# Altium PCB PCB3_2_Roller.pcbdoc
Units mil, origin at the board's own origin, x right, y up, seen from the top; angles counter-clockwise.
Board outline 1564.33 x 2054.84 mil, 2 copper layers (Top Layer, Bottom Layer), stack 2.757 mil thick; 8 components, 9 nets, 34 pads, 9 vias.
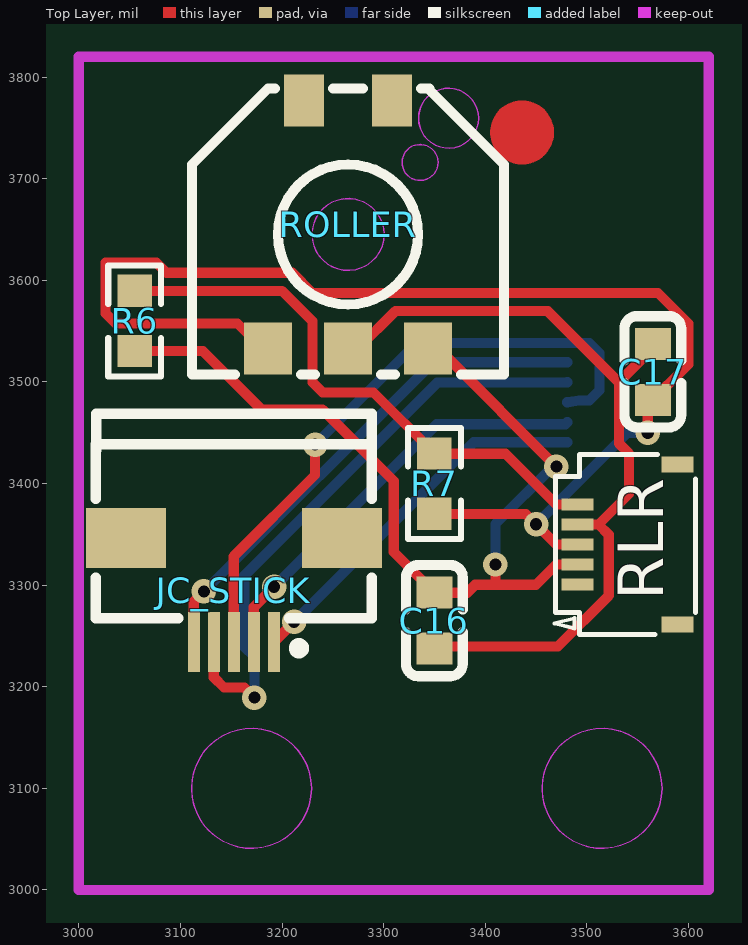
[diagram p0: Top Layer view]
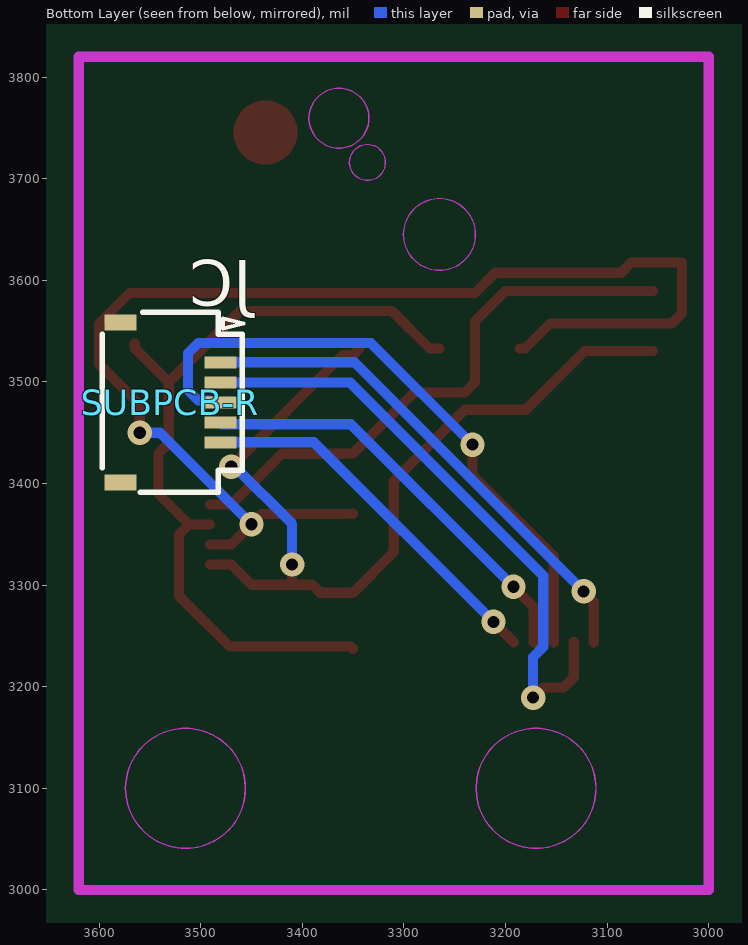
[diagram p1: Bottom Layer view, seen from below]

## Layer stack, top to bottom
Top Solder Mask Layer: solder mask 0.394, Dk 3.3
Top Layer: signal copper 1.379
Bottom Layer: signal copper 1.378
Bottom Solder Mask Layer: solder mask 0.394, Dk 3.3

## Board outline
4314.33,2750 2750,2750 2750,4804.84 4314.33,4804.84

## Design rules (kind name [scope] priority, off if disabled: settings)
BoardOutlineClearance Default [All] p0: genericclearance=10 ignorepadtopadclearanceinfootprint=FALSE except(0: Arc-SplitContinuation Track-SplitContinuation SMDPad-SplitContinuation THPad-SplitContinuation Via-SplitContinuation Fill-SplitContinuation Poly-SplitContinuation Region-SplitContinuation Text-SplitContinuation)
BoardOutlineClearance otherClearance [All] p0: genericclearance=10 ignorepadtopadclearanceinfootprint=FALSE except(0: Arc-SplitContinuation Track-SplitContinuation SMDPad-SplitContinuation THPad-SplitContinuation Via-SplitContinuation Fill-SplitContinuation Poly-SplitContinuation Region-SplitContinuation Text-SplitContinuation)
Clearance Default [All] p1: gap=7 ignorepadtopadclearanceinfootprint=FALSE
Clearance otherClearance [All] p1: gap=7 ignorepadtopadclearanceinfootprint=FALSE
DiffPairsRouting differentialPair [All] p1: maxuncoupledlength=10 minlimit=5 maxlimit=Infinity mostfreqgap=6 toplayer_minwidth=5 toplayer_prefwidth=100 toplayer_maxwidth=100 bottomlayer_minwidth=5 bottomlayer_prefwidth=100 bottomlayer_maxwidth=100
PasteMaskExpansion pasteMaskExpansion [All] p1: expansion=0
PlaneConnect innerPlane [All] p1: planeconnectstyle=Relief reliefexpansion=20 reliefentries=4 reliefconductorwidth=10 reliefairgap=10
PolygonConnect copperRegion [All] p1: connectstyle=Relief reliefentries=4 reliefconductorwidth=10 polygonreliefangle="90 Angle" airgapwidth=10
RoutingVias Default [All] p1: viastyle="Through Hole" holewidth=12.008000000000001 minholewidth=12.008000000000001 maxholewidth=1181 width=12.008000000000001 minwidth=12.008000000000001 maxwidth=1181
SolderMaskExpansion Common [IsVia] p1: useseparateexpansions=TRUE expansion=-1000 expansionbottom=-1000
SolderMaskExpansion Common [All] p2: useseparateexpansions=TRUE expansion=2 expansionbottom=2
Width Default [All] p1: maxlimit=1000 minlimit=10 preferedwidth=10

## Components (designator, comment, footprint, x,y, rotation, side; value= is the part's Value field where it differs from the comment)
C16 "0.1uF" C0603 3350,3265 r90 top
C17 "0.1uF" C0603 3565,3510 r90 top
JC_STICK "JOYCON STICK" 任天堂SWITCH摇杆 3152.52,3295 r180 top
R6 "10kΩ" R0603 3055,3560 r270 top
R7 "10kΩ" R0603 3350,3400 r270 top
RLR "Roller" CONN-SMD_5P-P0.50_HCTL_HC-FPC-05-09-5RLTAG 3540,3340 r90 top
ROLLER "YTS23-E0035-A1B" SW-SMD_YTS23-E0035-A1B 3265,3655 r0 top
SUBPCB-R "Roller" CONN-SMD_5P-P0.50_HCTL_HC-FPC-05-09-5RLTAG 3530,3480 r270 bottom

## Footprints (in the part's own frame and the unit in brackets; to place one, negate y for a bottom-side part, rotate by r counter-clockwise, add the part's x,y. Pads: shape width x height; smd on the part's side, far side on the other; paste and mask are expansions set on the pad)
C0603 [mm]
  rect 0.8x0.9 smd paste+0 mask+0.051: 1(-0.7,0) 2(0.7,0)
  silkscreen extent -1.39,-0.71 1.39,0.71
CONN-SMD_5P-P0.50_HCTL_HC-FPC-05-09-5RLTAG [mm]
  rect 0.3x0.8 smd paste+0 mask+0.051: 1(-1,1.25) 2(-0.5,1.25) 3(0,1.25) 4(0.5,1.25) 5(1,1.25)
  rect 0.4x0.8 smd paste+0 mask+0.051: 6(2,-1.25) 7(-2,-1.25)
  silkscreen extent -2.25,-1.7 2.25,1.83
R0603 [mil]
  rect 31.75x34.02 smd paste-3937.01 mask+2: 1(-29.66,0) 2(29.66,0)
  silkscreen extent -55,-26 55,26
SW-SMD_YTS23-E0035-A1B [mm]
  rect 1.2x1.3 smd paste+0 mask+0.051: A(-2,-3.1) B(2,-3.1) C(0,-3.1)
  rect 1x1.3 smd paste+0 mask+0.051: D(-1.1,3.1) E(1.1,3.1)
  Top Layer lines w0.8: 3.95,2.3 cw(c4.35,2.3) 4.75,2.3 cw(c4.35,2.3) 3.95,2.3
  Board Outline Layer circle w0.003: c0,-0.25 r0.9
  Board Outline Layer circle w0.003: c1.8,1.55 r0.45
  Board Outline Layer region: 0.9,-0.25 0.811,-0.641 0.561,-0.954 0.2,-1.128 -0.2,-1.128 -0.561,-0.954 -0.811,-0.641 -0.9,-0.25 -0.9,-0.25 -0.811,0.14 -0.561,0.453 -0.2,0.627 0.2,0.627 0.561,0.453 0.811,0.14 0.9,-0.25
  Board Outline Layer region: 0.9,-0.25 0.811,-0.641 0.561,-0.954 0.2,-1.128 -0.2,-1.128 -0.561,-0.954 -0.811,-0.641 -0.9,-0.25 -0.9,-0.25 -0.811,0.14 -0.561,0.453 -0.2,0.627 0.2,0.627 0.561,0.453 0.811,0.14 0.9,-0.25
  Board Outline Layer region: 2.25,1.55 2.206,1.355 2.081,1.198 1.9,1.111 1.7,1.111 1.52,1.198 1.395,1.355 1.35,1.55 1.35,1.55 1.395,1.745 1.52,1.902 1.7,1.989 1.9,1.989 2.081,1.902 2.206,1.745 2.25,1.55
  Board Outline Layer region: 2.25,1.55 2.206,1.355 2.081,1.198 1.9,1.111 1.7,1.111 1.52,1.198 1.395,1.355 1.35,1.55 1.35,1.55 1.395,1.745 1.52,1.902 1.7,1.989 1.9,1.989 2.081,1.902 2.206,1.745 2.25,1.55
  silkscreen extent -3.9,-3.75 3.9,3.4
任天堂SWITCH摇杆 [mm]
  rect 0.3x1.5 smd paste+0 mask+0.051: 1(-1,1.3) 2(-0.5,1.3) 3(0,1.3) 4(0.5,1.3) 5(1,1.3)
  rect 2x1.5 smd paste+0 mask+0.051: 6(-2.7,-1.3) 7(2.7,-1.3)
  Board Outline Layer circle w0.003: c-21.25,-29.93 r0.6
  Board Outline Layer circle w0.003: c-5.37,-11.8 r0.75
  Board Outline Layer region: -21.85,-29.93 -21.79,-29.67 -21.624,-29.461 -21.383,-29.345 -21.116,-29.345 -20.876,-29.461 -20.709,-29.67 -20.65,-29.93 -20.65,-29.93 -20.709,-30.19 -20.876,-30.399 -21.116,-30.515 -21.383,-30.515 -21.624,-30.399 -21.79,-30.19 -21.85,-29.93
  Board Outline Layer region: -21.85,-29.93 -21.79,-29.67 -21.624,-29.461 -21.383,-29.345 -21.116,-29.345 -20.876,-29.461 -20.709,-29.67 -20.65,-29.93 -20.65,-29.93 -20.709,-30.19 -20.876,-30.399 -21.116,-30.515 -21.383,-30.515 -21.624,-30.399 -21.79,-30.19 -21.85,-29.93
  Board Outline Layer region: -6.12,-11.8 -6.046,-11.475 -5.837,-11.214 -5.537,-11.069 -5.203,-11.069 -4.902,-11.214 -4.694,-11.475 -4.62,-11.8 -4.62,-11.8 -4.694,-12.125 -4.902,-12.386 -5.203,-12.531 -5.537,-12.531 -5.837,-12.386 -6.046,-12.125 -6.12,-11.8
  Board Outline Layer region: -6.12,-11.8 -6.046,-11.475 -5.837,-11.214 -5.537,-11.069 -5.203,-11.069 -4.902,-11.214 -4.694,-11.475 -4.62,-11.8 -4.62,-11.8 -4.694,-12.125 -4.902,-12.386 -5.203,-12.531 -5.537,-12.531 -5.837,-12.386 -6.046,-12.125 -6.12,-11.8
  silkscreen extent -3.45,-4.41 3.45,1.58

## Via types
v1: diameter 24.02, hole 12.01, Top Layer to Bottom Layer, 9 vias

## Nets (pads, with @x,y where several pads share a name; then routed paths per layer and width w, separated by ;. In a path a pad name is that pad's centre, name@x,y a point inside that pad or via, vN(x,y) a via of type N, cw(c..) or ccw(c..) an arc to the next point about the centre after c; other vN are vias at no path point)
JC_STICK1_1: JC_STICK.1 SUBPCB-R.5 | length 370.4
  Top Layer w10: JC_STICK.1 v1(3211.89,3263.82)
  Bottom Layer w10: v1(3211.89,3263.82) 3388.7,3440.63 SUBPCB-R.5
JC_STICK1_2: JC_STICK.2 SUBPCB-R.4 | length 418.5
  Top Layer w10: JC_STICK.2 3172.21,3278.35 v1(3192.21,3298.35)
  Bottom Layer w10: v1(3192.21,3298.35) 3352.21,3458.35 3478.82,3458.35 SUBPCB-R.4
JC_STICK1_3: JC_STICK.3 SUBPCB-R.3 | length 625.8
  Top Layer w10: JC_STICK.3 3152.52,3328.35 3232.52,3408.35 v1(3232.52,3438.35)
  Bottom Layer w10: v1(3232.52,3438.35) 3332.52,3538.35 3502.52,3538.35 3512.52,3528.35 3512.52,3491.73 3502.52,3481.73 3492.52,3481.73 SUBPCB-R.3
JC_STICK1_4: JC_STICK.4 SUBPCB-R.2 | length 603.8
  Top Layer w10: JC_STICK.4 3132.84,3209.29 3142.84,3199.29 3162.84,3199.29 v1(3172.84,3189.29)
  Bottom Layer w10: v1(3172.84,3189.29) 3172.84,3229.29 3162.84,3239.29 3162.84,3309.29 3352.84,3499.29 3480.39,3499.29 SUBPCB-R.2
JC_STICK1_5: JC_STICK.5 SUBPCB-R.1 | length 505.2
  Top Layer w10: JC_STICK.5 3113.15,3283.82 v1(3123.15,3293.82)
  Bottom Layer w10: v1(3123.15,3293.82) 3348.7,3519.37 SUBPCB-R.1
SUB_3V3: R6.1 R7.1 RLR.5 | length 557.9
  Top Layer w10: R6.1 3200,3589.66 3230,3559.66 3230,3499.66 3240,3489.66 3290,3489.66 R7.1 3360.04,3429.37 3420.04,3429.37 3470.04,3379.37 RLR.5
SUB_A: C17.1 R7.2 RLR.3 ROLLER.A | length 1247.5
  Top Layer w10: ROLLER.A@3186.26,3532.95 3180.8,3532.95 3156.26,3557.49 3036.26,3557.49 3026.26,3567.49 3026.26,3617.49 3076.26,3617.49 3086.26,3607.49 3210.04,3607.49 3230.04,3587.49 3570.04,3587.49 3600.04,3557.49 3600.04,3517.49 3560.04,3477.49 v1(3560.04,3450) ; R7.2 3360.04,3370 3440.04,3370 v1(3450.04,3360) 3470.04,3340 RLR.3
  Bottom Layer w10: v1(3450.04,3360) 3540.04,3450 v1(3560.04,3450)
SUB_B: C16.2 R6.2 RLR.2 ROLLER.B | length 904.6
  Top Layer w10: R6.2 3122.23,3530.34 3180,3472.56 3240,3472.56 3310,3402.56 3310,3332.56 C16.2 3382.3,3292.56 3390.04,3300.31 3410.04,3300.31 ; ROLLER.B@3343.74,3532.95 3350.04,3526.65 3360.04,3526.65 v1(3470.04,3416.65) ; v1(3410.04,3320.31) 3410.04,3300.31 ; RLR.2 3470.04,3320.31 3450.04,3300.31 3410.04,3300.31
  Bottom Layer w10: v1(3410.04,3320.31) 3410.04,3360.31 3466.38,3416.65 v1(3470.04,3416.65)
SUB_GND: C16.1 C17.2 RLR.4 ROLLER.C | length 807.1
  Top Layer w10: ROLLER.C@3265,3532.95 3274.81,3532.95 3311.54,3569.68 3461.54,3569.68 3531.54,3499.68 ; C16.1 3352.24,3239.68 3471.54,3239.68 3521.54,3289.68 3521.54,3349.68 3511.54,3359.68 ; RLR.4 3511.54,3359.68 ; C17.2 3565,3533.15 3531.54,3499.68 ; 3511.54,3359.68 3541.54,3389.68 3541.54,3429.68 3531.54,3439.68 3531.54,3499.68
pads on no net: JC_STICK.6 JC_STICK.7 RLR.1 RLR.6 RLR.7 ROLLER.D ROLLER.E SUBPCB-R.6 SUBPCB-R.7

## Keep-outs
Board Outline Layer:
  region: 3229.05,3100 cw(c3170,3100) 3110.95,3100 cw(c3170,3100)
  circle w0.1: c3170,3100 r59.05
  region: 3229.05,3100 cw(c3170,3100) 3110.95,3100 cw(c3170,3100)
  region: 3574.05,3100 cw(c3515,3100) 3455.95,3100 cw(c3515,3100)
  circle w0.1: c3515,3100 r59.05
  region: 3574.05,3100 cw(c3515,3100) 3455.95,3100 cw(c3515,3100)
  lines w10: 3000,3000 3620,3000 3620,3820 3000,3820 3000,3000

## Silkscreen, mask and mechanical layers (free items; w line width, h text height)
Bottom Silkscreen Layer:
  text "JC" at 3450,3575 h45
Mechanical Layer:
  circle w0.1: c3170,3100 r59.05
  circle w0.1: c3515,3100 r59.05

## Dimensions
3000,3930 to 3620,3930 on Document Layer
